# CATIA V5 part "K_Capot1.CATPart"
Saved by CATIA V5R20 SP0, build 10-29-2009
Part number: Capot1
Bounding box of the stored display mesh (mm): x 30.5 to 33.5, y -29.999 to 229.999, z -30 to 80
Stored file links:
  G:\Khaled_CFAO_2011\SIL\SIL_GR1\mneves\Khaled\CAD_CATIA_Modifie\K_Capot1.CATPart
  G:\Khaled_CFAO_2011\SIL\SIL_GR1\mneves\Khaled\CAD_CATIA_Modifie\K_AssPince_A_Bois.CATProduct
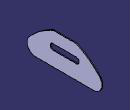
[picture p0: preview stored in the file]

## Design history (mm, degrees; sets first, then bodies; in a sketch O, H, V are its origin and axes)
External parameters (linked from other documents)
  External.Distance_Inter_Pivot = 200 mm
  External.Epaisseur_Cloison = 3 mm
Set1
  Plane1 "Plan_Capot1": linked copy from another document
  Line1: linked copy from another document
  Point1 "Centre_Pivot_Support2": linked copy from another document
  Point2 "Centre_Pivot_Support1": linked copy from another document
Body1 (main body)
  Sketch1 on Plane1, origin (30.5, 0, 0), H (0, 1, 0), V (0, 0, 1)
    line L1 (200, -30) -> (0, -30)
    point P1 (0, -30)
    reference projected line E1 (0, 0) -> (200, 0) from Line1
    arc A1 centre (200, 0) radius 30 from (200, -30) to (222.2183, 20.158) ccw
    point P3 (200, 0)
    reference projected point E2 (200, 0) from Point1
    arc A2 centre (0, 0) radius 30 from (-22.2183, 20.158) to (0, -30) ccw
    point P4 (0, 0)
    reference projected point E3 (0, 0) from Point2
    point P5 (140, 80)
    arc A3 centre (37.0658, -147.8257) radius 250 from (140, 80) to (222.2183, 20.158) cw
    line L2 (60, 80) -> (140, 80)
    point P8 (60, 80)
    reference projected point E4 (0, 0) from Point2
    reference projected point E5 (200, 0) from Point1
    point P10 (60, 80)
    arc A4 centre (162.9342, -147.8257) radius 250 from (60, 80) to (-22.2183, 20.158) ccw
    construction line L3 (59.5352, 30) -> (140.4648, 30)
    point P12 (59.5352, 30)
    point P13 (140.4648, 30)
    line L4 (59.5352, 40) -> (140.4648, 40)
    line L5 (140.4648, 20) -> (59.5352, 20)
    arc A5 centre (140.4648, 30) radius 10 from (140.4648, 40) to (140.4648, 20) cw
    arc A6 centre (59.5352, 30) radius 10 from (59.5352, 20) to (59.5352, 40) cw
    reference projected point E6 (0, 0) from Point2
    reference projected point E7 (200, 0) from Point1
    distance L1 E1 = 30 {= External.Distance_Inter_Pivot /8+External.Distance_Inter_Pivot /40}
    radius A3 = 250 {= External.Distance_Inter_Pivot *5/4}
    length L2 = 80 {= External.Distance_Inter_Pivot /2.5}
    distance P8 E4 = 100 {= External.Distance_Inter_Pivot /2}
    distance E5 P5 = 100 {= External.Distance_Inter_Pivot /2}
    radius A4 = 250 {= External.Distance_Inter_Pivot *5/4}
    distance L5 L1 = 50 {= External.Distance_Inter_Pivot /4}
    distance P12 E6 = 66.6667 {= External.Distance_Inter_Pivot /3}
    distance E7 P13 = 66.6667 {= External.Distance_Inter_Pivot /3}
    coincidence: P1 V, P3 E2, P4 E3, P10 P8
    horizontal: L1 H, L2 H
    tangency: A1 L1, A2 L1, A3 A1, A4 A2, L3 A1, A5 L4, A6 L4, A5 L5, A6 L5
    parallelism: L3 L4
  Pad1: profile Sketch1, direction (1, 0, 0), length 3 {= External.Epaisseur_Cloison}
